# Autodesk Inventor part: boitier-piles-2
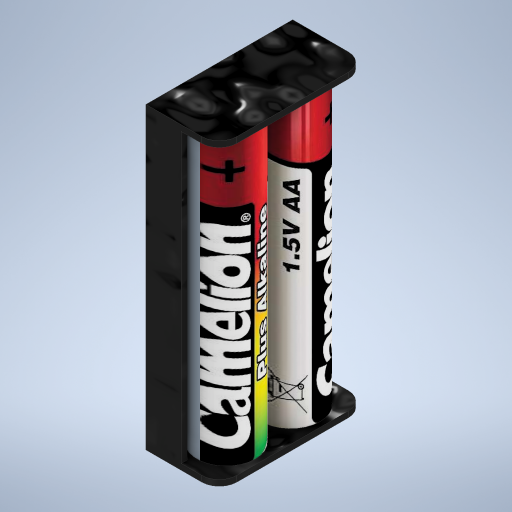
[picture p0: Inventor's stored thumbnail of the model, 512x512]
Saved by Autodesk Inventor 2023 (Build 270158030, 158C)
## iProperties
Created: 2022-01
Part Number: boitier-piles-2
Material: Générique
Document SubType Name: Modeling
Designer: bruno
Density: 1 g/cm^3
Appearance: Noir
Author: bruno
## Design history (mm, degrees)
sketch "Esquisse1"
  geometry: L1 (0, 0)-(51, 0); L2 (51, 0)-(51, -25); L3 (51, -25)-(0, -25); L4 (0, -25)-(0, 0)
  constraints: 8 end point, 2 parallel, 1 horizontal, 1 perpendicular
  dimensions: "d0" = 51 distance of L2.end L3.end; "d1" = 25 distance of L1.end L2.end
extrude "Extrusion1" new body sketch "Esquisse1" distance "d2" = 6; taper "d3" = 0 deg
feature "Coque1" dims "d4" = 1
sketch "Esquisse2"
  geometry: L1 (1, 50)-(1, 1) reference; L2 (1, 1)-(24, 1) reference; L3 (24, 1)-(24, 50) reference; L4 (24, 50)-(1, 50) reference; L5 (25, 51)-(0, 51) reference; L6 (0, 0)-(25, 0) reference; L7 (0, 0)-(25, 0); L8 (25, 0)-(25, 1); L9 (25, 1)-(0, 1); L10 (0, 1)-(0, 0); L11 (0, 51)-(25, 51); L12 (25, 51)-(25, 50); L13 (25, 50)-(0, 50); L14 (0, 50)-(0, 51); 6 further points
  constraints: 16 end point, 4 parallel, 2 horizontal, 2 perpendicular, 2 point on line
extrude "Extrusion2" join sketch "Esquisse2" distance "d5" = 6.5; taper "d6" = 0 deg
fillet "Congé1" dims "d7" = 3
sketch "Esquisse3"
  geometry: L1 (11.5, -21)-(11.5, -2) reference; L2 (-1, -24)-(8.5, -24) reference; L3 (-1, -24)-(-1, 1) reference; L4 (-1, 1)-(8.5, 1) reference; C1 r 5 at (5.656, -17); C2 r 5 at (5.656, -6); A1 r 3 centre (8.5, -2) between (11.5, -2) and (8.5, 1) reference; A2 r 3 centre (8.5, -21) between (8.5, -24) and (11.5, -21) reference; 1 further point
  constraints: 2 centre point
  dimensions: "d8" = 10 diameter of C1; "d9" = 10 diameter of C2; "d10" = 7 distance from line of L2 C1.centre; "d11" = 7 distance from line of L4 C2.centre
extrude "Extrusion3" join sketch "Esquisse3" stored distance "d12" = 6.5; taper "d13" = 0 deg
node "Plan de construction1"
sketch "Esquisse5"
  geometry: L1 (48.732, 21.883)-(48.732, 5.957); L2 (48.732, 5.957)-(-0.826, 5.957); L3 (-0.826, 5.957)-(-0.826, 21.883); L4 (-0.826, 21.883)-(48.732, 21.883); 1 further point; 1 other entity
  constraints: 2 other
feature "Décalcomanie2" sketch "Esquisse5"
sketch "Esquisse6"
  geometry: L1 (49.096, 4.989)-(49.096, -10.999); L2 (49.096, -10.999)-(-0.652, -10.999); L3 (-0.652, -10.999)-(-0.652, 4.989); L4 (-0.652, 4.989)-(49.096, 4.989); 1 further point; 1 other entity
  constraints: 2 other
feature "Décalcomanie3" sketch "Esquisse6"
node "Solide1"
node "Boucle projetée1"
node "Boucle projetée2"
node "Image3"
node "Image4"
